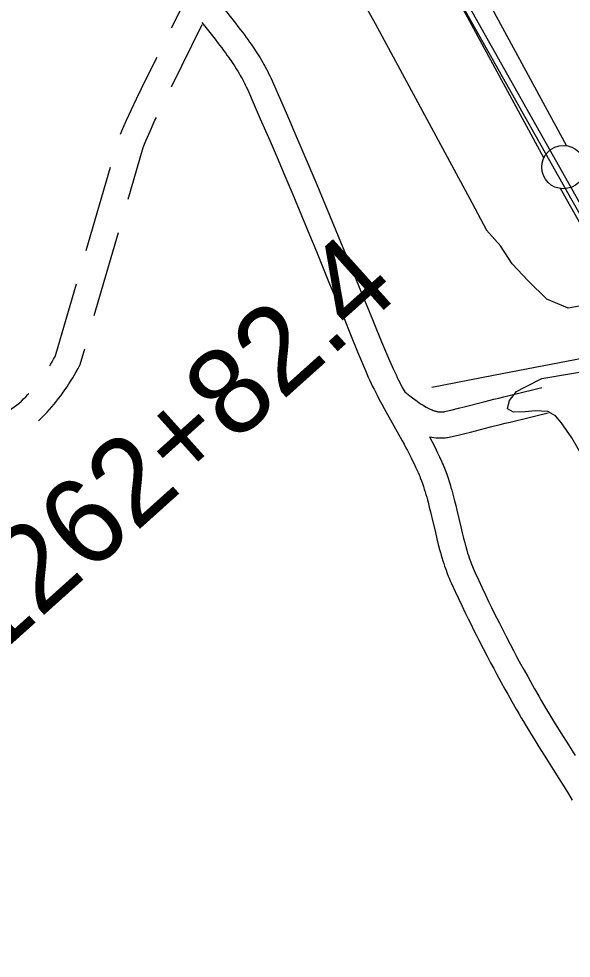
# Model space of a CAD drawing. Extents: x 3177185 to 3215018, y 812988 to 838321.
# Drawn here: x 3189152 to 3189789, y 829049 to 830133 of the extents above; entities that cross this region are included whole.
import ezdxf

# ---------------------------------------------------------------- set-up
doc = ezdxf.new("R2010")
doc.units = 0
for name, color, linetype in [('V-FLOD-BASE', 7, 'Continuous'), ('V-LEVE-TOET', 7, 'Continuous'), ('V-RAIL-TRAK', 7, 'Continuous'), ('V-RIVR-JETY', 7, 'Continuous'), ('V-ROAD-CNTR', 7, 'Continuous'), ('V-SURV-IDEN', 7, 'Continuous'), ('V-SURV-LINE', 7, 'Continuous')]:
    doc.layers.add(name, color=color, linetype=linetype)

msp = doc.modelspace()

# ---------------------------------------------------------------- linework, layer by layer
at = {"layer": 'V-FLOD-BASE'}
msp.add_lwpolyline([(3189628.3, 829708.1), (3189699.5, 829721.9), (3189841.7, 829749.1), (3189876.5, 829756.5), (3189877.2, 829757.1)], dxfattribs=at)
at = {"layer": 'V-LEVE-TOET'}
for points in [[(3188797.5, 831509.8), (3188940.2, 831252.7), (3189076.6, 831006.9), (3189153.4, 830855.8), (3189157.9, 830841.4), (3189171.1, 830813.9), (3189178.2, 830792.3), (3189180.3, 830783.6), (3189187.6, 830770), (3189195.8, 830757.4), (3189207.9, 830744), (3189221.6, 830728.5), (3189280, 830628.5), (3189394.3, 830429.5), (3189562.7, 830127.7), (3189674.3, 829921.1), (3189691.3, 829889.1)], [(3189161.3, 831409.9), (3189321.9, 831131.6), (3189472.7, 830847.3), (3189668.7, 830490), (3189779.2, 830281.6), (3189900.2, 830084.8), (3189961.7, 829980.4), (3189975.5, 829950), (3189972.7, 829924.1), (3189956.5, 829889.6), (3189938.1, 829867.3), (3189920.5, 829851.2), (3189904.4, 829840.1), (3189876.9, 829826.2), (3189841.7, 829809.4), (3189785.7, 829799.3), (3189761.1, 829809.8), (3189739.4, 829830.7), (3189721.1, 829850.6), (3189707.5, 829871.1), (3189691.3, 829889.1)]]:
    msp.add_lwpolyline(points, dxfattribs=at)
at = {"layer": 'V-RAIL-TRAK'}
msp.add_lwpolyline([(3187196.1, 834523.5), (3187196.3, 834523.3), (3187271.8, 834388.6), (3187402.7, 834157.5), (3187585, 833834.6), (3187750.8, 833540.2), (3187893.1, 833287.7), (3188030.9, 833043.5), (3188202.7, 832738.4), (3188367.6, 832447), (3188515.5, 832184.7), (3188604.4, 832027.3), (3188747.8, 831773.2), (3188901, 831502.1), (3189063.7, 831212.6), (3189216.3, 830943), (3189328.9, 830743), (3189498.1, 830440.7), (3189598.3, 830264.4), (3189789.8, 829924), (3189818.6, 829873.5), (3190149.3, 829287.6), (3190388.4, 828864.7)], dxfattribs=at)
at = {"layer": 'V-RIVR-JETY'}
msp.add_lwpolyline([(3190290.6, 828778.2), (3190181.1, 828965.2), (3189969.6, 829337.6), (3189790, 829649.6), (3189777.6, 829667.1), (3189770.9, 829675), (3189762.2, 829680), (3189747.6, 829680.8), (3189736, 829679.6), (3189722.7, 829679.2), (3189715.6, 829683), (3189718.1, 829692.5), (3189726.1, 829702.9), (3189735.6, 829707.9), (3189755.2, 829717.9), (3189818.9, 829729), (3189837.6, 829724.8), (3189852.1, 829718.5), (3189848.4, 829713.1), (3190094.3, 829275), (3190316.1, 828880.1)], dxfattribs=at)
at = {"layer": 'V-ROAD-CNTR'}
for p, q in [((3189327.9, 830122.8), (3189342.3, 830151.9)), ((3189327.8, 830054.8), (3189363.3, 830126.7)), ((3189229.5, 829865.9), (3189257.3, 829961.9)), ((3189238.8, 829790.6), (3189266.7, 829886.7))]:
    msp.add_line(p, q, dxfattribs=at)
for points in [[(3186813, 835225.2), (3189830.7, 829864.1), (3191892.3, 826207.1)], [(3189386.6, 830147.2), (3189401.7, 830128.1), (3189404.5, 830124.5), (3189407.2, 830121), (3189409.7, 830117.7), (3189412, 830114.7), (3189414.1, 830111.8), (3189416.2, 830109), (3189418, 830106.4), (3189419.8, 830103.9), (3189421.4, 830101.6), (3189422.9, 830099.4), (3189425.6, 830095.3), (3189428, 830091.6), (3189430, 830088.3), (3189431.8, 830085.4), (3189433.2, 830082.9), (3189434.5, 830080.6), (3189435.7, 830078.6), (3189437.5, 830075.1), (3189438.9, 830072.4), (3189439.9, 830070.3), (3189441.4, 830067.3), (3189442.8, 830064.2), (3189450.8, 830046), (3189457.8, 830030), (3189463.9, 830016), (3189469.2, 830003.8), (3189478.4, 829982.4), (3189485.2, 829966.3), (3189495.4, 829942.1), (3189505.5, 829917.9), (3189514.8, 829895.5), (3189522.9, 829875.9), (3189537, 829841.6), (3189547.5, 829815.9), (3189555.4, 829796.6), (3189561.4, 829782.2), (3189570.3, 829760.5), (3189574.8, 829749.7), (3189579.3, 829739), (3189580.9, 829735.3), (3189582.4, 829731.9), (3189583.9, 829728.5), (3189585.4, 829725.3), (3189587, 829722.2), (3189588.4, 829719.1), (3189589.9, 829716.2), (3189591.3, 829713.4), (3189594.2, 829707.8), (3189597, 829702.7)], [(3189362.9, 830128.9), (3189378.1, 830109.6), (3189380.8, 830106.1), (3189383.4, 830102.7), (3189385.8, 830099.6), (3189388, 830096.7), (3189390, 830094), (3189391.9, 830091.4), (3189393.6, 830089), (3189395.2, 830086.7), (3189396.7, 830084.6), (3189398, 830082.7), (3189400.5, 830078.9), (3189402.6, 830075.6), (3189404.4, 830072.7), (3189405.9, 830070.1), (3189407.2, 830067.9), (3189408.4, 830066), (3189409.3, 830064.3), (3189410.9, 830061.2), (3189412.1, 830058.9), (3189412.9, 830057.2), (3189414.2, 830054.6), (3189415.4, 830052), (3189423.4, 830033.9), (3189430.3, 830018), (3189436.4, 830004.1), (3189441.6, 829991.9), (3189450.8, 829970.6), (3189457.6, 829954.6), (3189467.8, 829930.5), (3189477.9, 829906.3), (3189487.1, 829884), (3189495.2, 829864.5), (3189509.2, 829830.2), (3189519.8, 829804.5), (3189527.7, 829785.2), (3189533.6, 829770.7), (3189542.6, 829749), (3189547.1, 829738.2), (3189551.7, 829727.3), (3189553.4, 829723.4), (3189555, 829719.6), (3189556.7, 829715.9), (3189558.3, 829712.4), (3189560, 829709), (3189561.6, 829705.8), (3189563.1, 829702.7), (3189564.7, 829699.6), (3189567.7, 829693.9), (3189570.5, 829688.5), (3189573.3, 829683.4), (3189593.7, 829646.7), (3189596.2, 829642.2), (3189598.3, 829638.2), (3189600.2, 829634.8), (3189601.7, 829631.7), (3189604.5, 829626.4), (3189606.4, 829622.4), (3189607.9, 829619.4), (3189610, 829614.9), (3189612, 829610.4), (3189612.8, 829608.7), (3189613.6, 829606.9), (3189614.3, 829605.2), (3189614.9, 829603.5), (3189616.2, 829600), (3189617.4, 829596.7), (3189618.6, 829593.4), (3189619.6, 829590.2), (3189620.6, 829587.1), (3189621.5, 829584), (3189622.4, 829581), (3189623.2, 829578.1), (3189623.9, 829575.2), (3189625.4, 829569.6), (3189626.7, 829564.3), (3189627.9, 829559.3), (3189632.4, 829540.1), (3189634.1, 829532.8), (3189635.7, 829526.4), (3189637.2, 829520.7), (3189638.5, 829515.9)], [(3189293.2, 830052.9), (3189299.2, 830064.6), (3189311.3, 830089.1)], [(3189269.1, 830000.1), (3189270.7, 830004.1), (3189276, 830016.4), (3189281.6, 830028.7), (3189287.3, 830040.8), (3189293.1, 830052.7)], [(3189277.9, 829925.1), (3189295.2, 829984.8), (3189298.4, 829992.4), (3189303.5, 830004.3), (3189308.8, 830016.1), (3189310.4, 830019.4)], [(3189187.3, 829732.8), (3189188.2, 829734.2), (3189190, 829737.3), (3189191.8, 829740.4), (3189193.5, 829743.6), (3189194.5, 829745.6), (3189218.3, 829827.5)], [(3189174.4, 829669.2), (3189175.6, 829670.4), (3189178.5, 829673.3), (3189181.4, 829676.2), (3189184.2, 829679.2), (3189187, 829682.3), (3189189.7, 829685.4), (3189192.4, 829688.5), (3189195, 829691.7), (3189197.6, 829694.9), (3189200.1, 829698.2), (3189202.5, 829701.5), (3189204.9, 829704.9), (3189207.3, 829708.3), (3189209.5, 829711.7), (3189211.7, 829715.2), (3189213.9, 829718.7), (3189216, 829722.3), (3189218, 829725.9), (3189220, 829729.5), (3189222.5, 829734.4), (3189227.7, 829752.2)], [(3189597, 829702.7), (3189602.8, 829698.2), (3189605.8, 829695.9), (3189608.7, 829693.8), (3189611.3, 829691.8), (3189613.8, 829690.1), (3189616, 829688.6), (3189618.1, 829687.3), (3189620, 829686.1), (3189621.8, 829685), (3189623.4, 829684.1), (3189624.9, 829683.4), (3189626.3, 829682.7), (3189627.6, 829682.1), (3189628.7, 829681.7), (3189629.8, 829681.2), (3189630.8, 829680.9), (3189631.7, 829680.6), (3189632.5, 829680.4), (3189633.2, 829680.2), (3189633.9, 829680), (3189634.6, 829679.8), (3189635.2, 829679.7), (3189635.6, 829679.7), (3189636.7, 829679.5), (3189637.6, 829679.4), (3189638.3, 829679.4), (3189639, 829679.4), (3189639.5, 829679.4), (3189639.9, 829679.4), (3189640.8, 829679.5), (3189641.4, 829679.5), (3189641.8, 829679.6), (3189642.6, 829679.7), (3189643.4, 829679.9), (3189651.7, 829681.9), (3189659, 829683.7), (3189665.5, 829685.3), (3189688.4, 829691.2), (3189699.9, 829694.1), (3189705.6, 829695.5), (3189711.4, 829696.9), (3189733.4, 829702.3), (3189744.4, 829704.9), (3189755.4, 829707.5)], [(3189082.5, 829642.4), (3189084.3, 829643.5), (3189107.3, 829658.5), (3189130, 829673.9), (3189151.8, 829689.1), (3189152, 829689.4), (3189154.7, 829691.9), (3189157.2, 829694.5), (3189159.8, 829697), (3189162.2, 829699.6), (3189163.3, 829700.8)], [(3189625.7, 829650.7), (3189633.3, 829649.7), (3189635.4, 829649.5), (3189637.2, 829649.4), (3189638.8, 829649.4), (3189640.2, 829649.4), (3189641.5, 829649.4), (3189643.5, 829649.6), (3189645.2, 829649.8), (3189646.5, 829649.9), (3189648.3, 829650.2), (3189650, 829650.6), (3189658.8, 829652.7), (3189666.3, 829654.6), (3189672.9, 829656.2), (3189695.8, 829662.1), (3189707.2, 829665), (3189712.8, 829666.4), (3189718.5, 829667.8), (3189740.5, 829673.1), (3189751.4, 829675.7), (3189762.4, 829678.3)], [(3189625.7, 829650.7), (3189631.3, 829639.9), (3189633.4, 829635.6), (3189634.9, 829632.4), (3189637.2, 829627.5), (3189639.5, 829622.6), (3189640.4, 829620.5), (3189641.2, 829618.5), (3189642.1, 829616.4), (3189642.9, 829614.4), (3189644.4, 829610.5), (3189645.8, 829606.6), (3189647, 829602.9), (3189648.2, 829599.3), (3189649.3, 829595.8), (3189650.3, 829592.4), (3189651.2, 829589.1), (3189652.1, 829585.9), (3189652.9, 829582.8), (3189654.5, 829576.9), (3189655.8, 829571.4), (3189657.1, 829566.2), (3189661.6, 829547), (3189663.2, 829539.9), (3189664.8, 829533.8), (3189666.2, 829528.5), (3189667.4, 829523.9)], [(3189667.4, 829524.1), (3189668.6, 829520), (3189669.6, 829516.6), (3189670.6, 829513.7), (3189671.4, 829511.1), (3189672.2, 829508.9), (3189672.9, 829507), (3189674.1, 829503.6), (3189675.1, 829501.1), (3189675.8, 829499.2), (3189677, 829496.5), (3189678.3, 829493.7), (3189682.4, 829484.7), (3189686.4, 829476.2), (3189690.2, 829468.2), (3189693.8, 829460.8), (3189697.1, 829453.8), (3189700.3, 829447.3), (3189703.4, 829441.2), (3189706.2, 829435.5), (3189708.9, 829430.2), (3189714.1, 829420.2), (3189718.6, 829411.5), (3189722.6, 829403.9), (3189726.1, 829397.3), (3189729.2, 829391.5), (3189734.7, 829381.4), (3189738.9, 829373.9), (3189742.1, 829368.2), (3189746.8, 829359.7), (3189751.6, 829351.3), (3189754.4, 829346.4), (3189757.1, 829341.7), (3189759.8, 829337.2), (3189762.5, 829332.8), (3189767.6, 829324.3), (3189772.5, 829316.4), (3189777.1, 829309), (3189785.9, 829295), (3189793.7, 829282.8)], [(3189638.6, 829515.7), (3189639.8, 829511.5), (3189641, 829507.7), (3189642, 829504.4), (3189643, 829501.5), (3189643.9, 829498.9), (3189644.7, 829496.7), (3189646.1, 829492.8), (3189647.2, 829489.9), (3189648.1, 829487.7), (3189649.5, 829484.5), (3189650.9, 829481.3), (3189655.2, 829472), (3189659.3, 829463.4), (3189663.1, 829455.3), (3189666.8, 829447.7), (3189670.2, 829440.6), (3189673.5, 829434), (3189676.5, 829427.8), (3189679.5, 829422), (3189682.2, 829416.6), (3189687.4, 829406.5), (3189692, 829397.6), (3189696.1, 829389.9), (3189699.7, 829383.2), (3189702.8, 829377.3), (3189708.4, 829367), (3189712.7, 829359.3), (3189715.9, 829353.6), (3189720.7, 829345), (3189725.6, 829336.4), (3189728.5, 829331.4), (3189731.3, 829326.5), (3189734.1, 829321.9), (3189736.8, 829317.3), (3189742, 829308.7), (3189747, 829300.6), (3189751.7, 829293), (3189760.6, 829279), (3189768.3, 829266.8), (3189775, 829256.1), (3189780.9, 829246.8), (3189785.9, 829238.6), (3189790.3, 829231.4)]]:
    msp.add_lwpolyline(points, dxfattribs=at)
at = {"layer": 'V-SURV-LINE'}
for points in [[(3189350.6, 830785.8), (3189783.8, 829986.8)], [(3189757.4, 829972.6), (3189324.3, 830771.5)], [(3191970.5, 826045.1), (3189776.9, 829937.4)]]:
    msp.add_lwpolyline(points, dxfattribs=at)
msp.add_circle((3189780.1, 829962.1), 25, dxfattribs=at)

# ---------------------------------------------------------------- texts
at = {"layer": 'V-SURV-IDEN'}
msp.add_text('1262+82.4', height=100, rotation=41.924, dxfattribs=at).set_placement((3189120.5, 829391))

doc.saveas('drawing.dxf')
